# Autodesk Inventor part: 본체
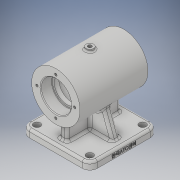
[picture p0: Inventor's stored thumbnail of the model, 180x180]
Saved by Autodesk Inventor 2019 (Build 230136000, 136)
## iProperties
Created: 2019-06
Part Number: 본체
Material: 알루미늄 6061
Document SubType Name: Modeling
Designer: SCD-A08
Density: 2.7 g/cm^3
Appearance: 알루미늄 - 평지
Mass: 228.506 g
Surface Area: 626.551 cm^2
Volume: 228.506 cm^3
Author: SCD-A08
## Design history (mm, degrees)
sketch "스케치1"
  geometry: L1 (0, 45)-(0, -45); L2 (32, 45)-(20, 45); L3 (20, -45)-(32, -45); L4 (32, -45)-(32, 45); L5 (19.4, 30)-(17, 30); L6 (17, 30)-(17, 24); L7 (17, 24)-(22, 24); L8 (32, 26.413)-(32, 33.764); L9 (22, -24)-(17, -24); L10 (17, -24)-(17, -30); L11 (17, -30)-(19.4, -30); L12 (32, -29.318)-(32, -19.232); L13 (25, 21)-(25, -21); L14 (32, -19.232)-(32, 26.413); L15 (20, 45)-(20, 30.6); L16 (20, -30.6)-(20, -45); A1 r 3 centre (22, 21) between (25, 21) and (22, 24); A2 r 3 centre (22, -21) between (22, -24) and (25, -21); A3 r 0.6 centre (19.4, -30.6) between (20, -30.6) and (19.4, -30); A4 r 0.6 centre (19.4, 30.6) between (19.4, 30) and (20, 30.6); 6 further points
  constraints: 32 end point, 11 point on line, 8 parallel, 8 point on circle, 8 tangent, 4 centre point, 4 perpendicular, 3 horizontal, 2 equal radius, 2 horizontal alignment, 1 coincident, 1 midpoint, 1 vertical
  dimensions: "d0" = 90 distance of L1.start L1.end; "d2" = 64 diameter of L4 L1; "d3" = 40 diameter of L15 L1; "d4" = 34 diameter of L6 L1; "d5" = 40 diameter of L16 L1; "d6" = 50 diameter of L13 L1; "d7" = 90 distance of L3.end L2.start; "d8" = 15 distance of L2.end point (20, 30); "d9" = 15 distance of point (20, -30) L3.start; "d10" = 48 distance of point (25, 24) point (25, -24); "d11" = 6 distance of L9.end L10.end; "d12" = 3 radius of A1; "d13" = 0.6 radius of A3
revolve "회전1" sketch "스케치1" stored, may be unused: angle "d14" = 90 deg
node "작업 평면1"
sketch "스케치2"
  geometry: L1 (35, 45)-(-35, 45); L2 (-45, 35)-(-45, -35); L3 (-35, -45)-(35, -45); L4 (45, -35)-(45, 35); L5 (45, 45)-(-45, -45); L6 (-45, 45)-(45, -45); C1 r 4.5 at (35, 35); C2 r 4.5 at (-35, 35); C3 r 4.5 at (-35, -35); C4 r 4.5 at (35, -35); A1 r 10 centre (35, 35) between (45, 35) and (35, 45); A2 r 10 centre (35, -35) between (35, -45) and (45, -35); A3 r 10 centre (-35, -35) between (-45, -35) and (-35, -45); A4 r 10 centre (-35, 35) between (-35, 45) and (-45, 35); 1 further point
  constraints: 12 end point, 8 centre point, 8 point on circle, 8 point on line, 8 tangent, 4 coincident, 3 equal radius, 2 midpoint, 2 parallel, 1 horizontal, 1 perpendicular
  dimensions: "d16" = 90 distance of L6.end L5.end; "d17" = 90 distance of L5.end L6.start; "d18" = 10 radius of A1; "d19" = 9 diameter of C1; "d20" = 9 diameter of C2; "d21" = 9 diameter of C3; "d22" = 9 diameter of C4
extrude "돌출1" join sketch "스케치2" distance "d23" = 10; taper "d24" = 0 deg
sketch "스케치3"
  geometry: L1 (-5, 35)-(5, 35); L2 (5, 35)-(5, -35); L3 (5, -35)-(-5, -35); L4 (-5, -35)-(-5, 35); L5 (-5, 35)-(5, -35); L6 (5, 35)-(-5, -35); 1 further point
  constraints: 12 end point, 2 midpoint, 2 parallel, 1 horizontal, 1 perpendicular
  dimensions: "d25" = 10 distance of L2.end L3.end; "d26" = 70 distance of L1.end L2.end
extrude "돌출2" join sketch "스케치3" stored distance "d27" = 10; taper "d28" = 0 deg
sketch "스케치5"
  geometry: C1 r 2 at (0, 25); 1 further point
  constraints: 1 centre point, 1 vertical alignment
  dimensions: "d35" = 4 diameter of C1; "d36" = 25 distance of point (0, 0) C1.centre
hole "구멍1" sketch "스케치5" at (0, 25) diameter "d37" = 3.242; stored, may be unused: countersink angle "d41" = 90 deg, drill point angle "d43" = 118 deg; dims "d38" = 7, "d39" = 4, "d40" = 2, "d42" = 9
sketch "스케치7"
  geometry: L1 (-22, 40)-(22, 40); L2 (40, 22)-(40, -22); L3 (22, -40)-(-22, -40); L4 (-40, -22)-(-40, 22); L5 (-40, 40)-(40, -40); L6 (40, 40)-(-40, -40); L7 (-35, 25)-(-37, 25); L8 (-25, 35)-(-25, 37); L9 (-25, -35)-(-25, -37); L10 (-35, -25)-(-37, -25); L11 (35, -25)-(37, -25); L12 (25, -35)-(25, -37); L13 (25, 35)-(25, 37); L14 (35, 25)-(37, 25); A1 r 10 centre (-35, 35) between (-35, 45) and (-45, 35) reference; A2 r 10 centre (-35, 35) between (-35, 25) and (-25, 35); A3 r 3 centre (-37, 22) between (-37, 25) and (-40, 22); A4 r 3 centre (-22, 37) between (-22, 40) and (-25, 37); A5 r 3 centre (-22, -37) between (-25, -37) and (-22, -40); A6 r 10 centre (-35, -35) between (-25, -35) and (-35, -25); A7 r 3 centre (-37, -22) between (-40, -22) and (-37, -25); A8 r 3 centre (37, -22) between (37, -25) and (40, -22); A9 r 10 centre (35, -35) between (35, -25) and (25, -35); A10 r 3 centre (22, -37) between (22, -40) and (25, -37); A11 r 3 centre (22, 37) between (25, 37) and (22, 40); A12 r 10 centre (35, 35) between (25, 35) and (35, 25); A13 r 3 centre (37, 22) between (40, 22) and (37, 25); 1 further point
  constraints: 28 end point, 24 point on circle, 12 centre point, 6 tangent, 2 horizontal, 2 midpoint, 2 parallel, 2 perpendicular, 2 point on line, 1 coincident, 1 equal radius, 57 other
  dimensions: "d49" = 20 diameter of A2; "d50" = 3 radius of A3 (derived); "d53" = 360 deg dimension on point (0, 0) L7.end (derived); "d55" = 80 distance between parallel lines of L2 L4
extrude "돌출4" cut sketch "스케치7" distance "d56" = 5; taper "d57" = 0 deg
node "작업 평면2"
sketch "스케치8"
  geometry: C1 r 5 at (0, 0); 1 further point
  constraints: 1 centre point, 1 coincident
  dimensions: "d67" = 10 diameter of C1
extrude "돌출5" join sketch "스케치8" stored distance "d68" = 5; taper "d69" = 0 deg
sketch "스케치9"
  geometry: C1 r 5 at (0, 0) reference; 2 further points
  constraints: 1 coincident
hole "구멍2" sketch "스케치9" at (0, 0) diameter "d70" = 4.917; stored, may be unused: countersink angle "d74" = 90 deg, drill point angle "d76" = 118 deg; dims "d71" = 12, "d72" = 4, "d73" = 2, "d75" = 17.1
fillet "모깎기1" dims "d61" = 3, "d62" = 3, "d82" = 2
chamfer "모따기1" distance "d63" = 1; stored, may be unused: second distance "d64" = 2, angle "d65" = 45 deg
node "작업 평면3"
sketch "스케치10"
  geometry: L1 (-65, -35)-(-65, 35) reference; L2 (-65, 45)-(-58, 45) reference; 2 further points
  constraints: 1 other
  dimensions: "d78" = 4 distance from line of L1 point (-61, 0); "d79" = 45 distance from line of L2 point (-61, 0)
feature "엠보싱1" sketch "스케치10" dims "d0" = 90, "d2" = 64, "d3" = 40, "d4" = 34, "d5" = 40, "d6" = 50, "d7" = 90, "d8" = 15, "d9" = 15, "d10" = 48, "d11" = 6, "d12" = 3, "d13" = 0.6, "d80" = 0.5, "d81" = 0
sketch "스케치11"
  geometry: L1 (-45, -65)-(-45, -58) reference; L2 (-35, -65)-(-35, -55); L3 (-39.5, -55)-(-30.5, -55) reference; L4 (-35, -55)-(-23.058, -22.189); L5 (-35, -55)-(17.931, -55); L6 (0, 0)-(0, -73.154); L7 (35, -55)-(23.058, -22.189); L8 (35, -55)-(-35, -55) reference; L9 (35, -55)-(-35, -55); A1 r 32 centre (0, 0) between (-23.058, -22.189) and (23.058, -22.189); 1 further point
  constraints: 12 end point, 2 horizontal, 2 point on circle, 2 symmetric about line, 1 centre point, 1 coincident, 1 midpoint, 1 parallel, 1 vertical
  dimensions: "d83" = 10 distance between parallel lines of L1 L2; "d84" = 70 deg angle of L5 L4; "d85" = 64 diameter of A1
extrude "돌출6" join sketch "스케치11" stored distance "d86" = 10; taper "d87" = 0 deg
fillet "모깎기2" dims "d88" = 3
node "솔리드1"
pattern_circular "원형 패턴1" dims angle "d59" = 360 deg
mirror "미러1"
other parameters: "d15" = -65, "d66" = 35
